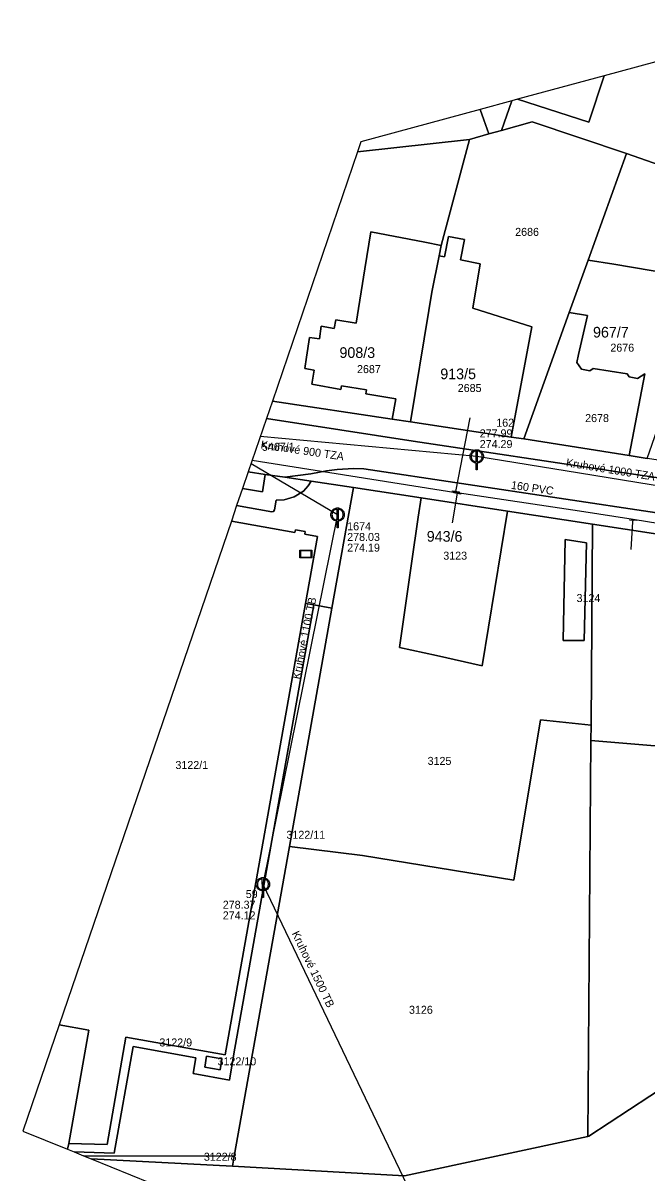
# Model space of a CAD drawing. Extents: x -570104 to -569328, y -1087857 to -1087418.
# Drawn here: x -570104.4 to -569987.5, y -1087663.8 to -1087448.3 of the extents above; entities that cross this region are included whole.
import ezdxf

# ---------------------------------------------------------------- set-up
doc = ezdxf.new("R2010")
doc.units = 0
for name, color, linetype in [('Adresní místo-text', 7, 'Continuous'), ('Armatura vodovodní', 7, 'Continuous'), ('Default', 7, 'Continuous'), ('Kanalizační stoka', 7, 'Continuous'), ('Kanalizační šachta', 7, 'Continuous'), ('Lapač olejů', 7, 'Continuous'), ('Parcela-polygon', 7, 'Continuous'), ('Parcela-text', 7, 'Continuous'), ('Popis kmenové stoky', 7, 'Continuous'), ('Popis šachty', 7, 'Continuous'), ('Vodovodní přípojka', 7, 'Continuous'), ('Vodovodní řad', 7, 'Continuous'), ('Řad vodovodní popis', 7, 'Continuous')]:
    doc.layers.add(name, color=color, linetype=linetype)

msp = doc.modelspace()

# ---------------------------------------------------------------- linework, layer by layer
at = {"layer": 'Armatura vodovodní'}
for points in [[(-570023.83, -1087535.9), (-570022.6, -1087536.14), (-570022.61, -1087536.22), (-570023.84, -1087535.98), (-570023.83, -1087535.9)], [(-570022.34, -1087536.53), (-570023.57, -1087536.33), (-570023.56, -1087536.25), (-570022.33, -1087536.45), (-570022.34, -1087536.53)], [(-569990.59, -1087541.37), (-569989.34, -1087541.43), (-569989.35, -1087541.51), (-569990.6, -1087541.45), (-569990.59, -1087541.37)]]:
    msp.add_lwpolyline(points, dxfattribs=at)
at = {"layer": 'Default'}
for points in [[(-570019.38, -1087530.74), (-570019.64, -1087530.72), (-570019.9, -1087530.57), (-570020.2, -1087530.41), (-570020.37, -1087530.11), (-570020.53, -1087529.81), (-570020.53, -1087529.49), (-570020.53, -1087529.16), (-570020.36, -1087528.86), (-570020.19, -1087528.56), (-570019.9, -1087528.4), (-570019.6, -1087528.24), (-570019.28, -1087528.24), (-570018.97, -1087528.24), (-570018.67, -1087528.4), (-570018.37, -1087528.56), (-570018.2, -1087528.86), (-570018.03, -1087529.16), (-570018.03, -1087529.49), (-570018.03, -1087529.81), (-570018.19, -1087530.11), (-570018.36, -1087530.41), (-570018.66, -1087530.57), (-570018.92, -1087530.72), (-570019.18, -1087530.74)], [(-570019.38, -1087528.45), (-570019.58, -1087528.47), (-570019.8, -1087528.58), (-570020.04, -1087528.72), (-570020.18, -1087528.97), (-570020.32, -1087529.22), (-570020.32, -1087529.49), (-570020.32, -1087529.76), (-570020.19, -1087530.01), (-570020.05, -1087530.25), (-570019.8, -1087530.39), (-570019.59, -1087530.51), (-570019.38, -1087530.53)], [(-570019.18, -1087530.53), (-570018.97, -1087530.51), (-570018.76, -1087530.39), (-570018.51, -1087530.25), (-570018.37, -1087530.01), (-570018.24, -1087529.76), (-570018.24, -1087529.49), (-570018.24, -1087529.22), (-570018.38, -1087528.97), (-570018.52, -1087528.72), (-570018.77, -1087528.58), (-570018.98, -1087528.47), (-570019.18, -1087528.45)], [(-570045.49, -1087541.64), (-570045.75, -1087541.62), (-570046.01, -1087541.47), (-570046.31, -1087541.31), (-570046.48, -1087541.01), (-570046.64, -1087540.71), (-570046.64, -1087540.39), (-570046.64, -1087540.06), (-570046.47, -1087539.76), (-570046.3, -1087539.46), (-570046.01, -1087539.3), (-570045.71, -1087539.14), (-570045.39, -1087539.14), (-570045.08, -1087539.14), (-570044.78, -1087539.3), (-570044.48, -1087539.46), (-570044.31, -1087539.76), (-570044.14, -1087540.06), (-570044.14, -1087540.39), (-570044.14, -1087540.71), (-570044.3, -1087541.01), (-570044.47, -1087541.31), (-570044.77, -1087541.47), (-570045.03, -1087541.62), (-570045.29, -1087541.64)], [(-570045.49, -1087539.35), (-570045.69, -1087539.37), (-570045.91, -1087539.48), (-570046.15, -1087539.62), (-570046.29, -1087539.87), (-570046.43, -1087540.12), (-570046.43, -1087540.39), (-570046.43, -1087540.66), (-570046.3, -1087540.91), (-570046.16, -1087541.15), (-570045.91, -1087541.29), (-570045.7, -1087541.41), (-570045.49, -1087541.43)], [(-570045.29, -1087541.43), (-570045.08, -1087541.41), (-570044.87, -1087541.29), (-570044.62, -1087541.15), (-570044.48, -1087540.91), (-570044.35, -1087540.66), (-570044.35, -1087540.39), (-570044.35, -1087540.12), (-570044.49, -1087539.87), (-570044.63, -1087539.62), (-570044.88, -1087539.48), (-570045.09, -1087539.37), (-570045.29, -1087539.35)], [(-570059.48, -1087610.91), (-570059.74, -1087610.89), (-570060, -1087610.75), (-570060.3, -1087610.59), (-570060.47, -1087610.29), (-570060.64, -1087609.99), (-570060.64, -1087609.67), (-570060.64, -1087609.34), (-570060.48, -1087609.04), (-570060.31, -1087608.74), (-570060.01, -1087608.58), (-570059.72, -1087608.41), (-570059.4, -1087608.41), (-570059.08, -1087608.41), (-570058.78, -1087608.57), (-570058.48, -1087608.73), (-570058.31, -1087609.02), (-570058.14, -1087609.32), (-570058.14, -1087609.65), (-570058.14, -1087609.98), (-570058.3, -1087610.27), (-570058.46, -1087610.57), (-570058.76, -1087610.74), (-570059.02, -1087610.89), (-570059.28, -1087610.91)], [(-570059.5, -1087608.62), (-570059.7, -1087608.64), (-570059.91, -1087608.76), (-570060.16, -1087608.89), (-570060.3, -1087609.15), (-570060.43, -1087609.4), (-570060.43, -1087609.67), (-570060.43, -1087609.94), (-570060.29, -1087610.18), (-570060.15, -1087610.43), (-570059.9, -1087610.56), (-570059.69, -1087610.68), (-570059.49, -1087610.7)], [(-570059.28, -1087610.69), (-570059.08, -1087610.68), (-570058.86, -1087610.56), (-570058.62, -1087610.42), (-570058.48, -1087610.17), (-570058.35, -1087609.92), (-570058.35, -1087609.65), (-570058.35, -1087609.38), (-570058.49, -1087609.13), (-570058.63, -1087608.88), (-570058.88, -1087608.75), (-570059.1, -1087608.64), (-570059.29, -1087608.62)]]:
    msp.add_open_spline(points, degree=3, dxfattribs=at)
at = {"layer": 'Kanalizační stoka'}
msp.add_line((-570059.39, -1087609.66), (-570031.63, -1087667.56), dxfattribs=at)
for points in [[(-570019.28, -1087529.49), (-570059.89, -1087525.75)], [(-569973.15, -1087536.98), (-570000, -1087532.62), (-570019.28, -1087529.49)], [(-570061.61, -1087530.81), (-570045.39, -1087540.39)], [(-570045.39, -1087540.39), (-570059.39, -1087609.66)]]:
    msp.add_lwpolyline(points, dxfattribs=at)
at = {"layer": 'Kanalizační šachta'}
for points in [[(-570019.38, -1087530.53), (-570019.38, -1087528.45)], [(-570019.18, -1087528.45), (-570019.18, -1087530.53)], [(-570019.18, -1087530.74), (-570019.18, -1087531.99), (-570019.38, -1087531.99), (-570019.38, -1087530.74)], [(-570045.49, -1087541.43), (-570045.49, -1087539.35)], [(-570045.29, -1087539.35), (-570045.29, -1087541.43)], [(-570045.29, -1087541.64), (-570045.29, -1087542.89), (-570045.49, -1087542.89), (-570045.49, -1087541.64)], [(-570059.49, -1087610.7), (-570059.5, -1087608.62)], [(-570059.29, -1087608.62), (-570059.28, -1087610.69)], [(-570059.28, -1087610.91), (-570059.27, -1087612.16), (-570059.47, -1087612.16), (-570059.48, -1087610.91)]]:
    msp.add_lwpolyline(points, dxfattribs=at)
at = {"layer": 'Lapač olejů'}
for points in [[(-570052.49, -1087548.51), (-570052.49, -1087547.02), (-570050.19, -1087547.02), (-570050.19, -1087548.51), (-570052.49, -1087548.51)], [(-570050.34, -1087548.36), (-570050.34, -1087547.17), (-570052.35, -1087547.17), (-570052.35, -1087548.36), (-570050.34, -1087548.36)]]:
    msp.add_lwpolyline(points, dxfattribs=at)
at = {"layer": 'Parcela-polygon'}
for p, q in [((-569980.67, -1087454.14), (-569995.37, -1087458.13)), ((-569995.37, -1087458.13), (-570011.66, -1087462.55)), ((-570012.69, -1087462.83), (-570018.63, -1087464.44)), ((-570011.66, -1087462.55), (-570012.69, -1087462.83)), ((-570041.64, -1087472.37), (-570057.61, -1087519.1)), ((-570057.61, -1087519.1), (-570058.73, -1087522.38)), ((-570058.73, -1087522.38), (-570062.15, -1087532.37)), ((-570062.15, -1087532.37), (-570063.23, -1087535.52)), ((-570063.23, -1087535.52), (-570064.31, -1087538.7)), ((-570064.31, -1087538.7), (-570065.3, -1087541.6)), ((-570065.3, -1087541.6), (-570097.58, -1087636.02)), ((-570096.02, -1087659.3), (-570094.8, -1087659.8)), ((-570094.8, -1087659.8), (-570093, -1087660.53)), ((-570093, -1087660.53), (-570091.62, -1087661.09)), ((-570091.62, -1087661.09), (-570053.03, -1087676.75))]:
    msp.add_line(p, q, dxfattribs=at)
for points in [[(-570012.69, -1087462.83), (-570014.66, -1087468.38), (-570008.88, -1087466.76), (-569991.2, -1087472.68), (-569969.97, -1087480.14), (-569959, -1087448.25)], [(-569995.37, -1087458.13), (-569998.24, -1087466.81), (-570011.66, -1087462.55)], [(-570011.66, -1087462.55), (-569998.24, -1087466.81), (-569995.37, -1087458.13)], [(-570018.63, -1087464.44), (-570017.95, -1087466.38), (-570017.01, -1087469.05), (-570014.66, -1087468.38), (-570012.69, -1087462.83)], [(-570018.63, -1087464.44), (-570041.01, -1087470.52), (-570041.64, -1087472.37)], [(-570041.64, -1087472.37), (-570020.62, -1087470.06), (-570017.01, -1087469.05), (-570017.95, -1087466.38), (-570018.63, -1087464.44)], [(-570057.61, -1087519.1), (-570035.12, -1087522.47), (-570034.48, -1087518.66), (-570040.08, -1087517.74), (-570039.97, -1087517), (-570044.66, -1087516.24), (-570044.77, -1087516.96), (-570050.23, -1087515.96), (-570049.78, -1087513.33), (-570051.51, -1087513.03), (-570051.19, -1087510.86), (-570050.65, -1087507.2), (-570048.78, -1087507.46), (-570048.47, -1087505.07), (-570046.01, -1087505.53), (-570045.68, -1087503.88), (-570041.91, -1087504.53), (-570040.27, -1087494.35), (-570039.14, -1087487.38), (-570029.01, -1087489.35), (-570025.98, -1087489.94), (-570020.62, -1087470.06), (-570041.64, -1087472.37)], [(-570058.73, -1087522.38), (-570031.19, -1087526.59), (-569992.91, -1087532.34), (-569952.3, -1087538.33), (-569927.99, -1087541.86), (-569877.22, -1087549.43), (-569875.95, -1087546.54), (-569876.49, -1087546.53), (-569888.84, -1087544.55), (-569894.55, -1087543.63), (-569908.12, -1087541.44), (-569945.89, -1087536.17), (-569967.95, -1087532.74), (-569972.48, -1087532.07), (-569987.31, -1087529.88), (-569990.72, -1087529.33), (-570010.46, -1087526.2), (-570012.81, -1087525.84), (-570031.69, -1087522.99), (-570035.12, -1087522.47), (-570057.61, -1087519.1)], [(-569769.73, -1087563.25), (-569786.28, -1087559.57), (-569813.25, -1087555.99), (-569813.61, -1087557.16), (-569830.19, -1087554.86), (-569829.74, -1087553.51), (-569837.58, -1087552.32), (-569857.97, -1087549.25), (-569872.59, -1087547.05), (-569875.95, -1087546.54), (-569877.22, -1087549.43), (-569927.99, -1087541.86), (-569952.3, -1087538.33), (-569992.91, -1087532.34), (-570031.19, -1087526.59), (-570058.73, -1087522.38)], [(-570063.23, -1087535.52), (-570059.47, -1087536.13), (-570058.95, -1087532.84), (-570062.15, -1087532.37)], [(-570062.15, -1087532.37), (-570058.95, -1087532.84), (-570055.3, -1087533.38), (-570050.38, -1087532.72), (-570047.44, -1087532.16), (-570045.45, -1087531.92), (-570042.42, -1087531.77), (-570040.43, -1087531.83), (-569985.51, -1087540.02), (-569937.05, -1087547.13), (-569910.3, -1087551.09), (-569891.52, -1087553.88), (-569876.46, -1087556.17), (-569847.79, -1087560.78), (-569823.32, -1087564.49), (-569791.66, -1087569.4), (-569779.9, -1087571.5)], [(-569985.51, -1087540.02), (-570040.43, -1087531.83), (-570042.42, -1087531.77), (-570045.45, -1087531.92), (-570047.44, -1087532.16), (-570050.38, -1087532.72), (-570055.3, -1087533.38), (-570050.35, -1087534.12), (-570042.42, -1087535.3), (-570029.72, -1087537.25), (-570013.51, -1087539.73), (-569997.57, -1087542.16), (-569973.1, -1087545.91)], [(-570065.3, -1087541.6), (-570053.38, -1087543.72), (-570053.29, -1087543.23), (-570051.43, -1087543.56), (-570051.51, -1087544.05), (-570049.12, -1087544.47), (-570051.38, -1087557.02), (-570049.84, -1087557.3), (-570046.45, -1087557.92), (-570042.42, -1087535.3), (-570050.35, -1087534.12), (-570050.87, -1087534.96), (-570051.8, -1087535.98), (-570053.51, -1087537.04), (-570055.41, -1087537.59), (-570056.91, -1087537.7), (-570057.2, -1087539.49), (-570057.41, -1087539.8), (-570057.74, -1087539.87), (-570064.31, -1087538.7)], [(-570064.31, -1087538.7), (-570057.74, -1087539.87), (-570057.41, -1087539.8), (-570057.2, -1087539.49), (-570056.91, -1087537.7), (-570055.41, -1087537.59), (-570053.51, -1087537.04), (-570051.8, -1087535.98), (-570050.87, -1087534.96), (-570050.35, -1087534.12), (-570055.3, -1087533.38), (-570058.95, -1087532.84), (-570059.47, -1087536.13), (-570063.23, -1087535.52)], [(-570097.58, -1087636.02), (-570092.01, -1087637.02), (-570095.79, -1087658.21), (-570088.61, -1087658.43), (-570085.06, -1087638.29), (-570066.46, -1087641.59), (-570051.38, -1087557.02), (-570049.12, -1087544.47), (-570051.51, -1087544.05), (-570051.43, -1087543.56), (-570053.29, -1087543.23), (-570053.38, -1087543.72), (-570065.3, -1087541.6)], [(-570094.8, -1087659.8), (-570087.29, -1087660.03), (-570083.74, -1087640.09), (-570071.97, -1087642.19), (-570072.48, -1087645.15), (-570065.67, -1087646.35), (-570064.84, -1087641.44), (-570049.84, -1087557.3), (-570051.38, -1087557.02), (-570066.46, -1087641.59), (-570085.06, -1087638.29), (-570088.61, -1087658.43), (-570095.79, -1087658.21), (-570096.02, -1087659.3)], [(-570093, -1087660.53), (-570064.75, -1087660.62), (-570054.41, -1087602.6), (-570046.45, -1087557.92), (-570049.84, -1087557.3), (-570064.84, -1087641.44), (-570065.67, -1087646.35), (-570072.48, -1087645.15), (-570071.97, -1087642.19), (-570083.74, -1087640.09), (-570087.29, -1087660.03), (-570094.8, -1087659.8)], [(-569950.93, -1087718.19), (-569943.15, -1087637.09), (-569942.1, -1087626.14), (-569950.39, -1087629.56), (-569962.74, -1087634.75), (-569975.37, -1087641.86), (-569998.28, -1087656.87), (-569998.44, -1087656.9), (-570032.83, -1087664.27), (-570065.08, -1087662.47), (-570091.62, -1087661.09)], [(-570097.58, -1087636.02), (-570104.38, -1087655.91), (-570096.02, -1087659.3)], [(-570096.02, -1087659.3), (-570095.79, -1087658.21), (-570092.01, -1087637.02), (-570097.58, -1087636.02)], [(-570067.08, -1087642.39), (-570067.41, -1087644.44), (-570070.3, -1087643.94), (-570069.96, -1087641.9), (-570067.08, -1087642.39)], [(-570091.62, -1087661.09), (-570065.08, -1087662.47), (-570064.75, -1087660.62), (-570093, -1087660.53)]]:
    msp.add_lwpolyline(points, dxfattribs=at)
for points in [[(-570012.81, -1087525.84), (-570010.46, -1087526.2), (-570001.94, -1087502.53), (-569998.4, -1087492.67), (-569991.2, -1087472.68), (-570008.88, -1087466.76), (-570014.66, -1087468.38), (-570017.01, -1087469.05), (-570020.62, -1087470.06), (-570025.98, -1087489.94), (-570026.36, -1087491.86), (-570025.33, -1087492.07), (-570024.59, -1087488.24), (-570021.6, -1087488.81), (-570022.35, -1087492.66), (-570018.67, -1087493.4), (-570020.05, -1087501.71), (-570008.96, -1087505.18)], [(-569998.4, -1087492.67), (-569993.61, -1087493.47), (-569986.61, -1087494.65), (-569975.67, -1087496.48), (-569972.34, -1087486.92), (-569969.97, -1087480.14), (-569991.2, -1087472.68)], [(-570048.47, -1087505.07), (-570048.78, -1087507.46), (-570050.65, -1087507.2), (-570051.19, -1087510.86), (-570051.51, -1087513.03), (-570049.78, -1087513.33), (-570050.23, -1087515.96), (-570044.77, -1087516.96), (-570044.66, -1087516.24), (-570039.97, -1087517), (-570040.08, -1087517.74), (-570034.48, -1087518.66), (-570035.12, -1087522.47), (-570031.69, -1087522.99), (-570028.3, -1087502.12), (-570027.73, -1087498.71), (-570026.36, -1087491.86), (-570025.98, -1087489.94), (-570029.01, -1087489.35), (-570039.14, -1087487.38), (-570040.27, -1087494.35), (-570041.91, -1087504.53), (-570045.68, -1087503.88), (-570046.01, -1087505.53)], [(-570031.69, -1087522.99), (-570012.81, -1087525.84), (-570008.96, -1087505.18), (-570020.05, -1087501.71), (-570018.67, -1087493.4), (-570022.35, -1087492.66), (-570021.6, -1087488.81), (-570024.59, -1087488.24), (-570025.33, -1087492.07), (-570026.36, -1087491.86), (-570027.73, -1087498.71), (-570028.3, -1087502.12)], [(-569990.72, -1087529.33), (-569987.31, -1087529.88), (-569978.52, -1087504.64), (-569975.67, -1087496.48), (-569986.61, -1087494.65), (-569993.61, -1087493.47), (-569998.4, -1087492.67), (-570001.94, -1087502.53), (-569998.49, -1087503.1), (-570000.22, -1087510.37), (-570000.51, -1087511.87), (-569999.62, -1087513.15), (-569998.07, -1087513.42), (-569997.44, -1087513.03), (-569991.05, -1087514.01), (-569990.7, -1087514.57), (-569989.12, -1087514.9), (-569987.78, -1087514.01)], [(-570010.46, -1087526.2), (-569990.72, -1087529.33), (-569987.78, -1087514.01), (-569989.12, -1087514.9), (-569990.7, -1087514.57), (-569991.05, -1087514.01), (-569997.44, -1087513.03), (-569998.07, -1087513.42), (-569999.62, -1087513.15), (-570000.51, -1087511.87), (-570000.22, -1087510.37), (-569998.49, -1087503.1), (-570001.94, -1087502.53)], [(-569997.86, -1087579.86), (-569997.57, -1087542.16), (-570013.51, -1087539.73), (-570018.3, -1087568.7), (-570026.86, -1087566.81), (-570033.77, -1087565.28), (-570031.49, -1087549.53), (-570030.24, -1087540.87), (-570029.72, -1087537.25), (-570042.42, -1087535.3), (-570046.45, -1087557.92), (-570054.41, -1087602.6), (-570040.73, -1087604.24), (-570012.36, -1087608.91), (-570007.34, -1087578.85)], [(-570033.77, -1087565.28), (-570026.86, -1087566.81), (-570018.3, -1087568.7), (-570013.51, -1087539.73), (-570029.72, -1087537.25), (-570030.24, -1087540.87), (-570031.49, -1087549.53)], [(-569997.88, -1087582.73), (-569973.85, -1087584.72), (-569973.7, -1087579.41), (-569973.18, -1087559.65), (-569972.91, -1087549.54), (-569973.1, -1087545.91), (-569997.57, -1087542.16), (-569997.86, -1087579.86)], [(-570002.7, -1087545.04), (-569998.7, -1087545.65), (-569999.14, -1087563.95), (-570003.1, -1087564)], [(-570003.1, -1087564), (-569999.14, -1087563.95), (-569998.7, -1087545.65), (-570002.7, -1087545.04)], [(-570012.36, -1087608.91), (-570040.73, -1087604.24), (-570054.41, -1087602.6), (-570064.75, -1087660.62), (-570065.08, -1087662.47), (-570032.83, -1087664.27), (-569998.44, -1087656.9), (-569997.88, -1087582.73), (-569997.86, -1087579.86), (-570007.34, -1087578.85)], [(-569997.88, -1087582.73), (-569998.44, -1087656.9), (-569998.28, -1087656.87), (-569975.37, -1087641.86), (-569973.85, -1087584.72)], [(-570067.08, -1087642.39), (-570069.96, -1087641.9), (-570070.3, -1087643.94), (-570067.41, -1087644.44)]]:
    msp.add_lwpolyline(points, close=True, dxfattribs=at)
at = {"layer": 'Vodovodní přípojka'}
for points in [[(-570023.23, -1087536.21), (-570023.22, -1087536.06), (-570020.55, -1087522.22)], [(-570022.93, -1087536.24), (-570022.95, -1087536.39), (-570023.87, -1087541.93)], [(-569990.35, -1087546.91), (-569990.03, -1087541.76), (-569989.97, -1087541.44), (-569989.97, -1087541.25)]]:
    msp.add_lwpolyline(points, dxfattribs=at)
at = {"layer": 'Vodovodní řad'}
msp.add_lwpolyline([(-570061.4, -1087530.18), (-570023.23, -1087536.21), (-570022.93, -1087536.24), (-570000, -1087539.65), (-569989.97, -1087541.25), (-569977.64, -1087543.22), (-569977.37, -1087543.25), (-569965.32, -1087544.88), (-569950.19, -1087547.31), (-569948.61, -1087547.45), (-569940.38, -1087548.6), (-569923.12, -1087551.32), (-569918.14, -1087552.01), (-569908.48, -1087553.55), (-569895.01, -1087555.43), (-569894.19, -1087555.5), (-569885.09, -1087557.02)], dxfattribs=at)

# ---------------------------------------------------------------- texts
at = {"layer": 'Adresní místo-text'}
for s, p in [('967/7', (-569997.48, -1087507.2)), ('908/3', (-570045.03, -1087511.02)), ('913/5', (-570026.12, -1087515.01)), ('943/6', (-570028.66, -1087545.46))]:
    msp.add_text(s, height=2, dxfattribs=at).set_placement(p)
at = {"layer": 'Parcela-text'}
for s, p in [('2686', (-570012.08, -1087488.15)), ('2676', (-569994.23, -1087509.85)), ('2687', (-570041.74, -1087513.87)), ('2685', (-570022.85, -1087517.4)), ('2678', (-569998.96, -1087523.04)), ('5467/1', (-570059.57, -1087528.43)), ('3123', (-570025.56, -1087548.83)), ('3124', (-570000.57, -1087556.77)), ('3122/1', (-570075.79, -1087588.06)), ('3125', (-570028.5, -1087587.29)), ('3122/11', (-570054.97, -1087601.13)), ('3126', (-570031.99, -1087633.93)), ('3122/9', (-570078.8, -1087640.05)), ('3122/10', (-570067.89, -1087643.59)), ('3122/8', (-570070.46, -1087661.47))]:
    msp.add_text(s, height=1.5, dxfattribs=at).set_placement(p)
at = {"layer": 'Popis kmenové stoky'}
for s, rotation, p in [('Kruhové 900 TZA', 351.7046, (-570059.87, -1087527.97)), ('Kruhové 1000 TZA', 350.7766, (-570002.62, -1087531.32)), ('Kruhové 1100 TB', 78.574, (-570052.44, -1087571.33)), ('Kruhové 1500 TB', 295.6153, (-570054.02, -1087618.86))]:
    msp.add_text(s, height=1.5, rotation=rotation, dxfattribs=at).set_placement(p)
at = {"layer": 'Popis šachty'}
for s, p in [('162', (-570015.63, -1087523.91)), ('277.99', (-570018.73, -1087525.91)), ('274.29', (-570018.73, -1087527.91)), ('1674', (-570043.58, -1087543.32)), ('278.03', (-570043.58, -1087545.32)), ('274.19', (-570043.58, -1087547.32)), ('59', (-570062.6, -1087612.24)), ('278.37', (-570066.91, -1087614.24)), ('274.12', (-570066.91, -1087616.24))]:
    msp.add_text(s, height=1.5, dxfattribs=at).set_placement(p)
at = {"layer": 'Řad vodovodní popis'}
msp.add_text(' 160 PVC', height=1.5, rotation=351.7184, dxfattribs=at).set_placement((-570013.48, -1087535.46))

doc.saveas('drawing.dxf')
